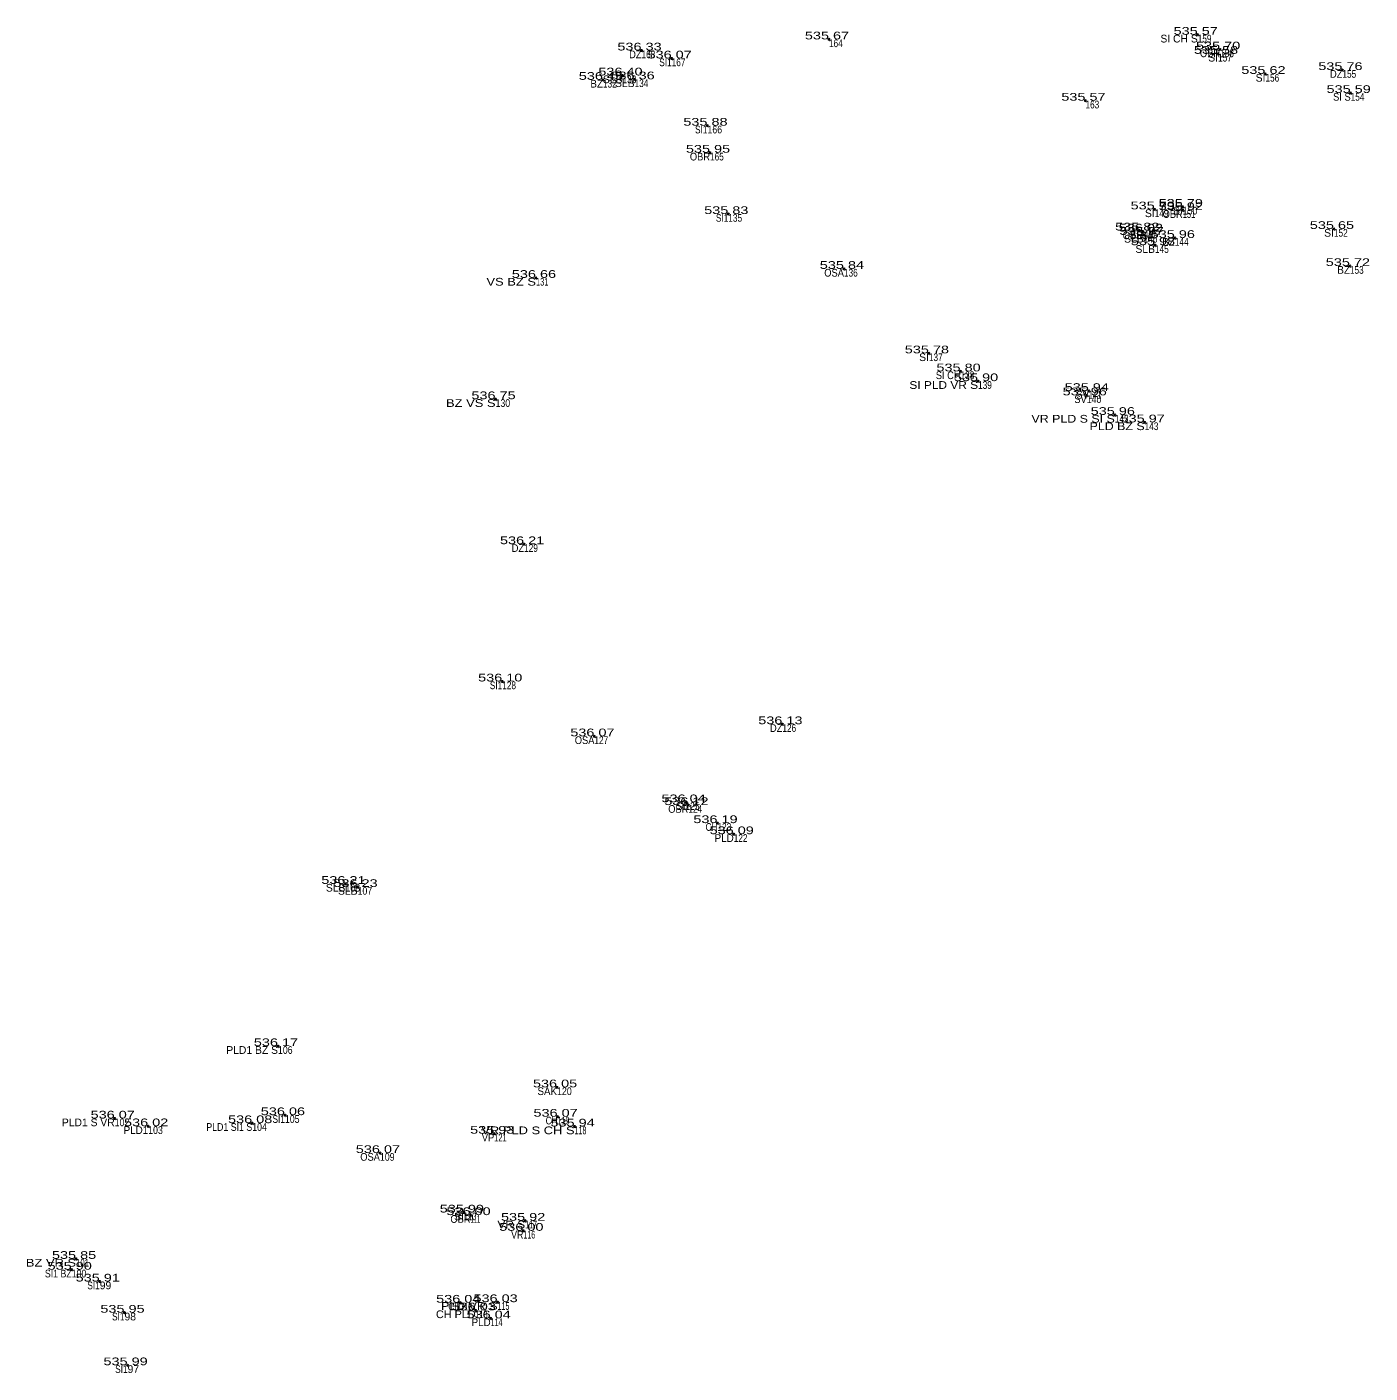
# Model space of a CAD drawing. Extents: x -643086 to -639283, y -1131805 to -1123269.
# Drawn here: x -642986.2 to -642934, y -1131402 to -1131349.8 of the extents above; entities that cross this region are included whole.
import ezdxf
from ezdxf.enums import TextEntityAlignment as Align

# ---------------------------------------------------------------- set-up
doc = ezdxf.new("R2010")
doc.units = 0
doc.header["$LTSCALE"] = 0.12
doc.header["$PDMODE"] = 32
doc.header["$PDSIZE"] = 0.06
for name, color, linetype in [('1', 7, 'Continuous'), ('2', 7, 'Continuous'), ('3', 7, 'Continuous'), ('4', 7, 'Continuous')]:
    doc.layers.add(name, color=color, linetype=linetype)

msp = doc.modelspace()

# ---------------------------------------------------------------- linework, layer by layer
at = {"layer": '1'}
for p in [(-642955.04, -1131350.25), (-642940.72, -1131350.07), (-642962.32, -1131350.68), (-642939.93, -1131350.81), (-642939.85, -1131350.64), (-642961.15, -1131350.99), (-642935.1, -1131351.44), (-642963.82, -1131351.82), (-642963.06, -1131351.65), (-642962.59, -1131351.8), (-642938.09, -1131351.59), (-642934.78, -1131352.33), (-642945.08, -1131352.63), (-642959.76, -1131353.6), (-642959.66, -1131354.65), (-642958.95, -1131357.03), (-642942.39, -1131356.85), (-642941.3, -1131356.75), (-642941.3, -1131356.88), (-642942.99, -1131357.67), (-642942.85, -1131357.71), (-642935.43, -1131357.61), (-642942.82, -1131357.84), (-642942.38, -1131358.24), (-642941.61, -1131357.96), (-642954.46, -1131359.16), (-642934.81, -1131359.05), (-642966.42, -1131359.51), (-642951.16, -1131362.44), (-642949.93, -1131363.14), (-642949.25, -1131363.52), (-642944.95, -1131363.9), (-642967.99, -1131364.22), (-642945.03, -1131364.07), (-642943.94, -1131364.83), (-642942.78, -1131365.12), (-642966.88, -1131369.85), (-642967.73, -1131375.18), (-642956.85, -1131376.84), (-642964.15, -1131377.31), (-642960.61, -1131379.87), (-642960.5, -1131379.98), (-642959.37, -1131380.68), (-642958.74, -1131381.11), (-642973.82, -1131383.04), (-642973.35, -1131383.16), (-642976.44, -1131389.34), (-642965.6, -1131390.94), (-642982.78, -1131392.15), (-642976.17, -1131392.02), (-642965.58, -1131392.08), (-642981.48, -1131392.45), (-642977.44, -1131392.33), (-642968.04, -1131392.74), (-642964.92, -1131392.46), (-642972.48, -1131393.49), (-642969.22, -1131395.8), (-642968.96, -1131395.9), (-642966.84, -1131396.12), (-642966.91, -1131396.51), (-642984.28, -1131397.6), (-642984.45, -1131398.02), (-642983.36, -1131398.48), (-642969.36, -1131399.3), (-642967.91, -1131399.28), (-642982.4, -1131399.69), (-642968.76, -1131399.6), (-642968.18, -1131399.91), (-642982.28, -1131401.73)]:
    msp.add_point(p, dxfattribs=at)

# ---------------------------------------------------------------- texts
at = {"layer": '2'}
for s, width, p in [('164', 0.8, (-642955.04, -1131350.55)), ('159', 0.8, (-642940.72, -1131350.37)), ('168', 0.8, (-642962.32, -1131350.98)), ('157', 0.8, (-642939.93, -1131351.11)), ('158', 0.8, (-642939.85, -1131350.94)), ('167', 0.8, (-642961.15, -1131351.29)), ('132', 0.8, (-642963.82, -1131352.12)), ('133', 0.8, (-642963.06, -1131351.95)), ('134', 0.8, (-642962.59, -1131352.1)), ('156', 0.8, (-642938.09, -1131351.89)), ('155', 0.8, (-642935.1, -1131351.74)), ('154', 0.8, (-642934.78, -1131352.63)), ('163', 0.8, (-642945.08, -1131352.93)), ('166', 0.85, (-642959.76, -1131353.9)), ('165', 0.8, (-642959.66, -1131354.95)), ('135', 0.8, (-642958.95, -1131357.33)), ('149', 0.8, (-642942.39, -1131357.15)), ('151', 0.7, (-642941.3, -1131357.18)), ('150', 0.85, (-642941.3, -1131357.05)), ('148', 0.8, (-642942.99, -1131357.97)), ('152', 0.8, (-642935.43, -1131357.91)), ('147', 0.8, (-642942.85, -1131358.01)), ('146', 0.8, (-642942.82, -1131358.14)), ('144', 0.8, (-642941.61, -1131358.26)), ('145', 0.8, (-642942.38, -1131358.54)), ('136', 0.8, (-642954.46, -1131359.46)), ('153', 0.8, (-642934.81, -1131359.35)), ('131', 0.7, (-642966.42, -1131359.81)), ('137', 0.8, (-642951.16, -1131362.74)), ('138', 0.8, (-642949.93, -1131363.44)), ('139', 0.8, (-642949.25, -1131363.82)), ('141', 0.7, (-642944.95, -1131364.2)), ('130', 0.85, (-642967.99, -1131364.52)), ('140', 0.85, (-642945.03, -1131364.37)), ('142', 0.8, (-642943.94, -1131365.13)), ('143', 0.8, (-642942.78, -1131365.42)), ('129', 0.8, (-642966.88, -1131370.15)), ('128', 0.8, (-642967.73, -1131375.48)), ('126', 0.8, (-642956.85, -1131377.14)), ('127', 0.8, (-642964.15, -1131377.61)), ('125', 0.8, (-642960.61, -1131380.17)), ('124', 0.8, (-642960.5, -1131380.28)), ('123', 0.8, (-642959.37, -1131380.98)), ('122', 0.8, (-642958.74, -1131381.41)), ('108', 0.85, (-642973.82, -1131383.34)), ('107', 0.85, (-642973.35, -1131383.46)), ('106', 0.85, (-642976.44, -1131389.64)), ('120', 0.85, (-642965.6, -1131391.24)), ('102', 0.85, (-642982.78, -1131392.45)), ('105', 0.85, (-642976.17, -1131392.32)), ('119', 0.55, (-642965.58, -1131392.38)), ('103', 0.85, (-642981.48, -1131392.75)), ('104', 0.85, (-642977.44, -1131392.63)), ('118', 0.55, (-642964.92, -1131392.76)), ('121', 0.7, (-642968.04, -1131393.04)), ('109', 0.85, (-642972.48, -1131393.79)), ('110', 0.6, (-642969.22, -1131396.1)), ('111', 0.45, (-642968.96, -1131396.2)), ('117', 0.55, (-642966.84, -1131396.42)), ('116', 0.55, (-642966.91, -1131396.81)), ('101', 0.75, (-642984.28, -1131397.9)), ('100', 0.85, (-642984.45, -1131398.32)), ('112', 0.55, (-642969.36, -1131399.6)), ('115', 0.55, (-642967.91, -1131399.58)), ('113', 0.55, (-642968.76, -1131399.9)), ('114', 0.55, (-642968.18, -1131400.21))]:
    msp.add_text(s, height=0.3, dxfattribs=dict(at, width=width)).set_placement(p)
for s, p in [('99', (-642983.36, -1131398.78)), ('98', (-642982.4, -1131399.99)), ('97', (-642982.28, -1131402.03))]:
    msp.add_text(s, height=0.3, dxfattribs=at).set_placement(p)
at = {"layer": '3', "width": 1.4}
for s, p in [('535 57 ', (-642940.72, -1131350.07)), ('536 33 ', (-642962.32, -1131350.68)), ('535 67 ', (-642955.04, -1131350.25)), ('535 70 ', (-642939.85, -1131350.64)), ('536 07 ', (-642961.15, -1131350.99)), ('535 58 ', (-642939.93, -1131350.81)), ('536 40 ', (-642963.06, -1131351.65)), ('535 62 ', (-642938.09, -1131351.59)), ('535 76 ', (-642935.1, -1131351.44)), ('536 45 ', (-642963.82, -1131351.82)), ('536 36 ', (-642962.59, -1131351.8)), ('535 57 ', (-642945.08, -1131352.63)), ('535 59 ', (-642934.78, -1131352.33)), ('535 88 ', (-642959.76, -1131353.6)), ('535 95 ', (-642959.66, -1131354.65)), ('535 79 ', (-642942.39, -1131356.85)), ('535 79 ', (-642941.3, -1131356.75)), ('535 92 ', (-642941.3, -1131356.88)), ('535 83 ', (-642958.95, -1131357.03)), ('535 82 ', (-642942.99, -1131357.67)), ('536 02 ', (-642942.85, -1131357.71)), ('535 97 ', (-642942.82, -1131357.84)), ('535 96 ', (-642941.61, -1131357.96)), ('535 65 ', (-642935.43, -1131357.61)), ('535 98 ', (-642942.38, -1131358.24)), ('536 66 ', (-642966.42, -1131359.51)), ('535 84 ', (-642954.46, -1131359.16)), ('535 72 ', (-642934.81, -1131359.05)), ('535 78 ', (-642951.16, -1131362.44)), ('535 80 ', (-642949.93, -1131363.14)), ('535 90 ', (-642949.25, -1131363.52)), ('536 75 ', (-642967.99, -1131364.22)), ('535 96 ', (-642945.03, -1131364.07)), ('535 94 ', (-642944.95, -1131363.9)), ('535 96 ', (-642943.94, -1131364.83)), ('535 97 ', (-642942.78, -1131365.12)), ('536 21 ', (-642966.88, -1131369.85)), ('536 10 ', (-642967.73, -1131375.18)), ('536 07 ', (-642964.15, -1131377.31)), ('536 13 ', (-642956.85, -1131376.84)), ('536 04 ', (-642960.61, -1131379.87)), ('536 12 ', (-642960.5, -1131379.98)), ('536 19 ', (-642959.37, -1131380.68)), ('536 09 ', (-642958.74, -1131381.11)), ('536 21 ', (-642973.82, -1131383.04)), ('536 23 ', (-642973.35, -1131383.16)), ('536 17 ', (-642976.44, -1131389.34)), ('536 05 ', (-642965.6, -1131390.94)), ('536 07 ', (-642982.78, -1131392.15)), ('536 02 ', (-642981.48, -1131392.45)), ('536 08 ', (-642977.44, -1131392.33)), ('536 06 ', (-642976.17, -1131392.02)), ('536 07 ', (-642965.58, -1131392.08)), ('535 94 ', (-642964.92, -1131392.46)), ('535 93 ', (-642968.04, -1131392.74)), ('536 07 ', (-642972.48, -1131393.49)), ('535 99 ', (-642969.22, -1131395.8)), ('536 00 ', (-642968.96, -1131395.9)), ('535 92 ', (-642966.84, -1131396.12)), ('536 00 ', (-642966.91, -1131396.51)), ('535 85 ', (-642984.28, -1131397.6)), ('535 90 ', (-642984.45, -1131398.02)), ('535 91 ', (-642983.36, -1131398.48)), ('536 03 ', (-642967.91, -1131399.28)), ('535 95 ', (-642982.4, -1131399.69)), ('536 04 ', (-642969.36, -1131399.3)), ('536 03 ', (-642968.76, -1131399.6)), ('536 04 ', (-642968.18, -1131399.91)), ('535 99 ', (-642982.28, -1131401.73))]:
    msp.add_text(s, height=0.3, dxfattribs=at).set_placement(p, align=Align.CENTER)
at = {"layer": '4'}
for s, p in [('SI CH S', (-642940.72, -1131350.37)), ('SI', (-642939.93, -1131351.11)), ('SLB', (-642963.06, -1131351.95)), ('SLB', (-642962.59, -1131352.1)), ('SI', (-642938.09, -1131351.89)), ('SI', (-642942.39, -1131357.15)), ('SI', (-642941.3, -1131357.05)), ('SI', (-642942.99, -1131357.97)), ('SI', (-642935.43, -1131357.91)), ('SLB', (-642942.82, -1131358.14)), ('SLB', (-642942.38, -1131358.54)), ('SI', (-642951.16, -1131362.74)), ('SI', (-642960.61, -1131380.17)), ('SLB', (-642973.82, -1131383.34)), ('SLB', (-642973.35, -1131383.46)), ('PLD1 BZ S', (-642976.44, -1131389.64)), ('PLD1 S VR', (-642982.78, -1131392.45)), ('SI', (-642969.22, -1131396.1))]:
    msp.add_text(s, height=0.3, dxfattribs=at).set_placement(p, align=Align.RIGHT)
for s, width, p in [('DZ', 0.9, (-642962.32, -1131350.98)), ('OBR', 0.9, (-642939.85, -1131350.94)), ('SI1', 0.8, (-642961.15, -1131351.29)), ('BZ', 0.95, (-642963.82, -1131352.12)), ('DZ', 0.9, (-642935.1, -1131351.74)), ('SI S', 0.9, (-642934.78, -1131352.63)), ('SI1', 0.8, (-642959.76, -1131353.9)), ('OBR', 0.9, (-642959.66, -1131354.95)), ('SI1', 0.8, (-642958.95, -1131357.33)), ('OBR', 0.9, (-642941.3, -1131357.18)), ('OBR', 0.9, (-642942.85, -1131358.01)), ('BZ', 0.95, (-642941.61, -1131358.26)), ('OSA', 0.9, (-642954.46, -1131359.46)), ('BZ', 0.95, (-642934.81, -1131359.35)), ('VS BZ S', 1.25, (-642966.42, -1131359.81)), ('SI CH', 0.9, (-642949.93, -1131363.44)), ('SI PLD VR S', 1.15, (-642949.25, -1131363.82)), ('SV', 0.9, (-642944.95, -1131364.2)), ('BZ VS S', 1.25, (-642967.99, -1131364.52)), ('SV', 0.9, (-642945.03, -1131364.37)), ('VR PLD S SI S', 1.2, (-642943.94, -1131365.13)), ('PLD BZ S', 1.2, (-642942.78, -1131365.42)), ('DZ', 0.9, (-642966.88, -1131370.15)), ('SI1', 0.8, (-642967.73, -1131375.48)), ('DZ', 0.9, (-642956.85, -1131377.14)), ('OSA', 0.9, (-642964.15, -1131377.61)), ('OBR', 0.9, (-642960.5, -1131380.28)), ('CH', 0.8, (-642959.37, -1131380.98)), ('PLD', 0.95, (-642958.74, -1131381.41)), ('SAK', 0.95, (-642965.6, -1131391.24)), ('SI1', 0.8, (-642976.17, -1131392.32)), ('CH', 0.8, (-642965.58, -1131392.38)), ('PLD1', 0.95, (-642981.48, -1131392.75)), ('PLD1 SI1 S', 0.85, (-642977.44, -1131392.63)), ('VR PLD S CH S', 1.25, (-642964.92, -1131392.76)), ('VP', 0.9, (-642968.04, -1131393.04)), ('OSA', 0.9, (-642972.48, -1131393.79)), ('OBR', 0.9, (-642968.96, -1131396.2)), ('VR S', 1.15, (-642966.84, -1131396.42)), ('VR', 0.85, (-642966.91, -1131396.81)), ('BZ VR S', 1.25, (-642984.28, -1131397.9)), ('SI1 BZ', 0.85, (-642984.45, -1131398.32)), ('SI1', 0.8, (-642983.36, -1131398.78)), ('PLD VR S', 1.2, (-642967.91, -1131399.58)), ('CH', 0.8, (-642969.36, -1131399.6)), ('SI1', 0.8, (-642982.4, -1131399.99)), ('CH PLD', 1.05, (-642968.76, -1131399.9)), ('PLD', 0.95, (-642968.18, -1131400.21)), ('SI1', 0.8, (-642982.28, -1131402.03))]:
    msp.add_text(s, height=0.3, dxfattribs=dict(at, width=width)).set_placement(p, align=Align.RIGHT)

doc.saveas('drawing.dxf')
